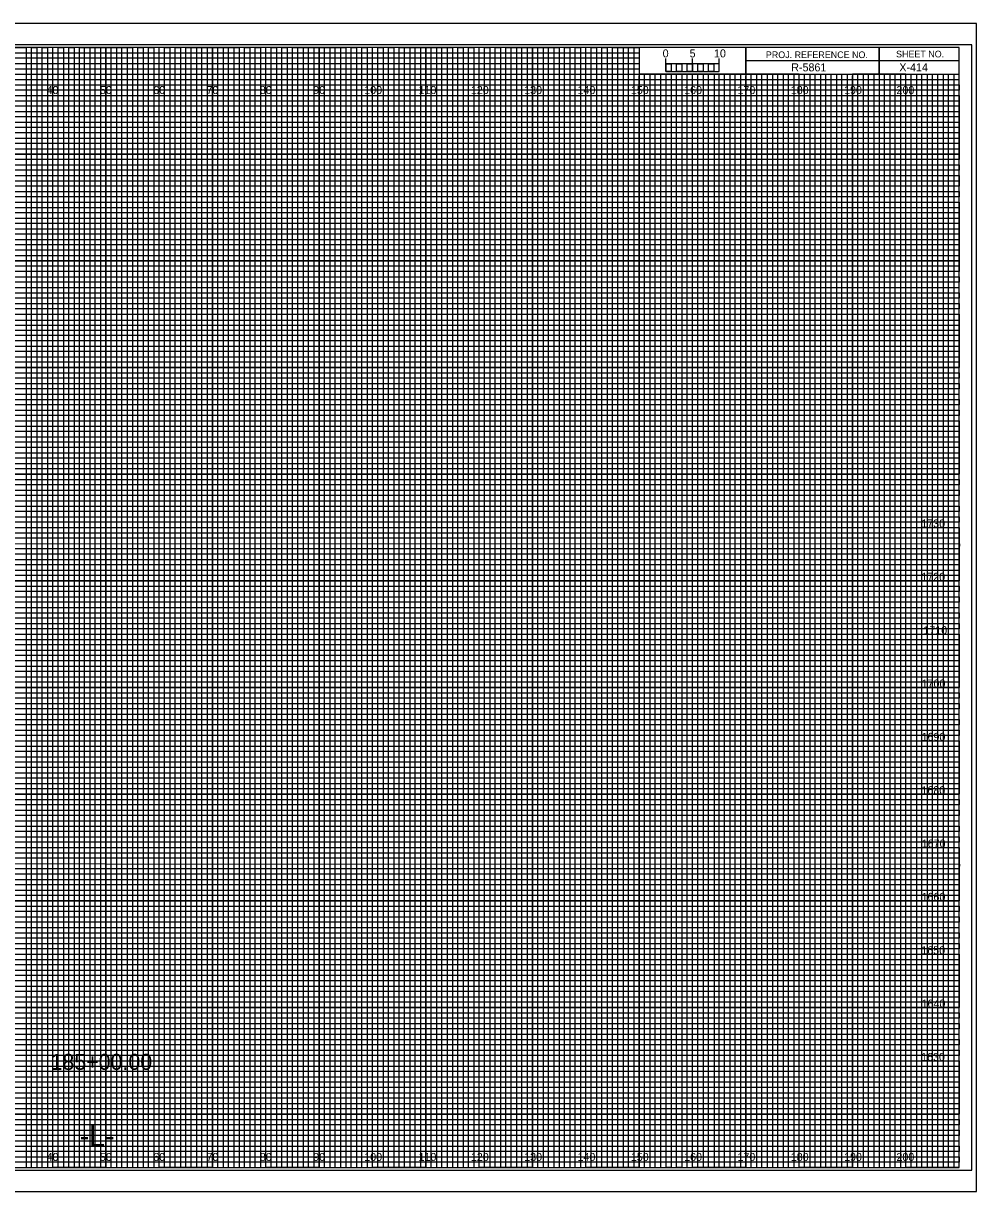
# Model space of a CAD drawing. Extents: x -13 to 323, y -5 to 6154.
# Drawn here: x 144.5 to 323.3, y 2195.5 to 2414.5 of the extents above; entities that cross this region are included whole.
import ezdxf

# ---------------------------------------------------------------- set-up
doc = ezdxf.new("R2010")
doc.units = 0
for name, color, linetype in [('Exist CMT Ground Line', 7, 'Continuous'), ('Prop Horizontal Alignment', 7, 'Continuous'), ('Prop Retaining Wall', 7, 'Continuous'), ('Prop XS Alignment Label', 7, 'Continuous'), ('Prop XS Bar Scale Labels', 7, 'Continuous'), ('Prop XS DDE', 7, 'Continuous'), ('Prop XS DDE Elevations', 7, 'Continuous'), ('Prop XS DDE Slope Text', 7, 'Continuous'), ('Prop XS Earthwork Shape', 7, 'Continuous'), ('Prop XS Elevation Labels', 7, 'Continuous'), ('Prop XS Project Number', 7, 'Continuous'), ('Prop XS Sheet Number', 7, 'Continuous'), ('Prop XS Station Labels', 7, 'Continuous'), ('Raster_Level_0', 7, 'Continuous'), ('Scratch_Level_3', 7, 'Continuous'), ('Sheet Cutting Line CELL', 7, 'Continuous')]:
    doc.layers.add(name, color=color, linetype=linetype)

msp = doc.modelspace()

# ---------------------------------------------------------------- linework, layer by layer
at = {"layer": 'Exist CMT Ground Line'}
for p, q in [((265, 2405.49), (265, 2407.9)), ((265, 2406.9), (265, 2407.9)), ((270, 2405.49), (270, 2407.9)), ((275, 2405.49), (275, 2407.9)), ((275, 2406.9), (275, 2407.9))]:
    msp.add_line(p, q, dxfattribs=at)
for points in [[(275, 2406.9), (265, 2406.9), (265, 2405.49), (275, 2405.49)], [(265, 2406.9), (266, 2406.9), (266, 2405.49), (265, 2405.49)], [(267, 2406.9), (268, 2406.9), (268, 2405.49), (267, 2405.49)], [(269, 2406.9), (270, 2406.9), (270, 2405.49), (269, 2405.49)], [(271, 2406.9), (272, 2406.9), (272, 2405.49), (271, 2405.49)], [(273, 2406.9), (274, 2406.9), (274, 2405.49), (273, 2405.49)]]:
    msp.add_lwpolyline(points, close=True, dxfattribs=at)
at = {"layer": 'Prop Retaining Wall'}
for p, q in [((0, 2409), (260, 2409)), ((260, 2409), (260, 2407.98)), ((260, 2407.98), (0, 2407.98)), ((0, 2407), (260, 2407)), ((260, 2407), (260, 2405.89)), ((260, 2405.89), (0, 2405.89)), ((0, 2404), (320, 2404))]:
    msp.add_line(p, q, dxfattribs=at)
for points in [[(0, 2403), (270, 2403), (320, 2403), (320, 2402), (0, 2402)], [(0, 2401), (320, 2401), (320, 2399), (0, 2399)], [(0, 2398), (320, 2398), (320, 2397), (0, 2396.98)], [(0, 2396), (320, 2396), (320, 2394), (0, 2394)], [(0, 2393), (320, 2393), (320, 2392), (0, 2392)], [(0, 2391), (320, 2391), (320, 2389), (0, 2389)], [(0, 2388), (320, 2388), (320, 2387), (0, 2387)], [(0, 2386), (320, 2386), (320, 2384), (0, 2384)], [(0, 2383), (320, 2383), (320, 2382), (0, 2382)], [(0, 2381), (320, 2381), (320, 2379), (0, 2379)], [(0, 2378), (320, 2378), (320, 2377), (0, 2377)], [(0, 2376), (320, 2376), (320, 2373.95), (320, 2373), (320, 2372), (0, 2372)], [(0, 2374), (320, 2374), (320, 2373), (0, 2373)], [(0, 2371), (320, 2371), (320, 2369), (0, 2369.03)], [(0, 2369.03), (320, 2369), (320, 2368), (0, 2368)], [(0, 2367), (320, 2367), (320, 2366), (0, 2366)], [(0, 2364), (320, 2364), (320, 2363), (0, 2363)], [(0, 2362), (320, 2362), (320, 2361), (0, 2361)], [(-0.07, 2358.89), (320, 2358.89), (320, 2357.88), (-0.07, 2357.88)], [(0, 2357), (320, 2357), (320, 2356), (0, 2356)], [(0, 2354), (320, 2354), (320, 2353), (0, 2353)], [(0, 2352), (320, 2352), (320, 2351), (0, 2351)], [(0, 2349), (320, 2349), (320, 2348), (0, 2348)], [(0, 2347), (320, 2347), (320, 2346), (0, 2346)], [(0, 2344), (320, 2344), (320, 2343), (0, 2343)], [(0, 2342), (320, 2342), (320, 2341), (0, 2341)], [(0, 2339), (320, 2339), (319.99, 2337.98), (0, 2338)], [(0, 2337), (320, 2337), (320, 2336), (0, 2336)], [(0, 2334), (320, 2334), (320, 2333), (0, 2333)], [(0, 2332), (320, 2332), (320, 2331), (0, 2331)], [(0, 2329), (320, 2329), (320, 2328), (0, 2328)], [(0, 2327), (320, 2327), (320, 2326), (0, 2326)], [(0, 2324), (320, 2324), (320, 2323), (0, 2323)], [(0, 2322), (320, 2322), (320, 2321), (0, 2321)], [(0, 2319), (320, 2319), (320, 2318), (0, 2318)], [(0, 2316.99), (320.07, 2316.91), (320, 2316), (0, 2316)], [(0, 2314), (320, 2314), (320, 2313), (0, 2313)], [(0, 2312), (320, 2312), (320, 2311), (0, 2311)], [(0, 2309), (320, 2309), (320, 2308), (0, 2308)], [(0, 2307), (320, 2307), (320, 2306), (0, 2306)], [(0, 2304), (320, 2304), (320, 2303), (0, 2303)], [(0, 2302), (320, 2302), (320, 2301), (0, 2301)], [(0, 2299), (320, 2299), (320, 2298), (0, 2298)], [(0, 2297), (320, 2297), (320, 2296), (0, 2296)], [(0, 2294), (320, 2294), (320, 2293), (0, 2293)], [(0, 2292), (320, 2292), (320, 2291), (0, 2291)], [(0, 2289), (320, 2289), (320, 2288), (0, 2288)], [(0, 2287), (320, 2287), (320, 2286), (0, 2286)], [(0, 2284), (320, 2284), (320, 2283), (0, 2283)], [(0, 2282), (320, 2282), (320, 2281), (0, 2281)], [(0, 2279), (320, 2279), (319.99, 2277.98), (0, 2278)], [(0, 2277), (320, 2277), (320, 2276), (0, 2276)], [(0, 2274), (320, 2274), (320, 2273), (0, 2273)], [(0, 2272), (320, 2272), (320, 2271), (0, 2271)], [(0, 2269), (320, 2269), (320, 2268), (0, 2268)], [(0, 2267), (320, 2267), (320, 2266), (0, 2266)], [(0, 2264), (320, 2264), (320, 2263), (0, 2263)], [(0, 2262), (320, 2262), (320, 2261), (0, 2261)], [(0, 2259), (320, 2259), (320, 2258), (0, 2258)], [(0, 2256.99), (320.07, 2256.91), (320, 2256), (0, 2256)], [(0, 2254), (320, 2254), (320, 2253), (0, 2253)], [(0, 2252), (320, 2252), (320, 2251), (0, 2251)], [(0, 2249), (320, 2249), (320, 2248), (0, 2248)], [(0, 2247), (320, 2247), (320, 2246), (0, 2246)], [(0, 2244), (320, 2244), (320, 2243), (0, 2243)], [(0, 2242), (320, 2242), (320, 2241), (0, 2241)], [(0, 2239), (320, 2239), (320, 2238), (0, 2238)], [(0, 2237), (320, 2237), (320, 2236), (0, 2236)], [(0, 2234), (320, 2234), (320, 2233), (0, 2233)], [(0, 2232), (320, 2232), (320, 2231), (0, 2231)], [(0, 2229), (320, 2229), (320, 2228), (0, 2228)], [(0, 2227), (320, 2227), (320, 2226), (0, 2226)], [(0, 2224), (320, 2224), (320, 2223), (0, 2223)], [(0, 2222), (320, 2222), (320, 2221), (0, 2221)], [(0, 2219), (320, 2219), (320, 2218), (0, 2218)], [(0, 2217), (320, 2217), (320, 2216), (0, 2216)], [(0, 2214), (320, 2214), (320, 2213), (0, 2213)], [(0, 2212), (320, 2212), (320, 2211), (0, 2211)], [(0, 2209), (320, 2209), (320, 2208), (0, 2208)], [(0, 2207), (320, 2207), (320, 2206), (0, 2206)], [(0, 2204), (320, 2204), (320, 2203), (0, 2203)], [(0, 2202), (320, 2202), (320, 2201), (0, 2201)]]:
    msp.add_lwpolyline(points, dxfattribs=at)
at = {"layer": 'Prop XS Alignment Label'}
for p, q in [((305, 2410), (305, 2405)), ((305, 2405), (305, 2410)), ((280, 2407.5), (280, 2405)), ((320, 2407.49), (280, 2407.49)), ((280, 2405), (320, 2405))]:
    msp.add_line(p, q, dxfattribs=at)
for points in [[(320, 2410), (0, 2410), (0, 2200), (320, 2200)], [(280, 2410), (260, 2410), (260, 2405.03), (280, 2405.03)], [(320, 2410), (280, 2410), (280, 2405), (320, 2405)]]:
    msp.add_lwpolyline(points, close=True, dxfattribs=at)
at = {"layer": 'Prop XS DDE'}
msp.add_lwpolyline([(-13.4, 2195.5), (323.3, 2195.5), (323.3, 2414.5), (-13.4, 2414.5)], close=True, dxfattribs=at)
at = {"layer": 'Prop XS DDE Elevations'}
for p, q in [((150, 2200), (150, 2410)), ((160, 2200), (160, 2410)), ((170, 2200), (170, 2410)), ((180, 2200), (180, 2410)), ((190, 2200), (190, 2410)), ((200, 2200), (200, 2410)), ((210, 2200), (210, 2410)), ((220, 2200), (220, 2410)), ((230, 2200), (230, 2410)), ((240, 2200), (240, 2410)), ((250, 2200), (250, 2410)), ((260, 2200), (260, 2404.69)), ((270, 2200), (270, 2404.69)), ((280, 2200), (280, 2404.69)), ((290, 2200), (290, 2404.69)), ((300, 2200), (300, 2404.69)), ((310, 2200), (310, 2404.69)), ((0, 2400), (320, 2400)), ((0, 2390), (320, 2390)), ((0, 2380), (320, 2380)), ((0, 2370), (320, 2370)), ((0, 2360), (320, 2360)), ((0, 2350), (320, 2350)), ((0, 2340), (320, 2340)), ((0, 2330), (320, 2330)), ((0, 2320), (320, 2320)), ((0, 2310), (320, 2310)), ((0, 2300), (320, 2300)), ((0, 2290), (320, 2290)), ((0, 2280), (320, 2280)), ((0, 2270), (320, 2270)), ((0, 2260), (320, 2260)), ((0, 2250), (320, 2250)), ((0, 2240), (320, 2240)), ((0, 2230), (320, 2230)), ((0, 2220), (320, 2220)), ((0, 2210), (320, 2210))]:
    msp.add_line(p, q, dxfattribs=at)
at = {"layer": 'Prop XS DDE Slope Text'}
msp.add_lwpolyline([(-10.8, 2199.5), (322.4, 2199.5), (322.4, 2410.5), (-10.8, 2410.5)], close=True, dxfattribs=at)
at = {"layer": 'Prop XS Earthwork Shape'}
for p, q in [((150, 2410), (140, 2410)), ((150, 2200), (150, 2410)), ((170, 2410), (160, 2410)), ((160, 2410), (160, 2200)), ((170, 2200), (170, 2410)), ((190, 2410), (180, 2410)), ((180, 2410), (180, 2200)), ((190, 2200), (190, 2410)), ((210, 2410), (200, 2410)), ((200, 2410), (200, 2200)), ((210, 2200), (210, 2410)), ((230, 2410), (220, 2410)), ((220, 2410), (220, 2200)), ((230, 2200), (230, 2410)), ((250, 2410), (240, 2410)), ((240, 2410), (240, 2200)), ((250, 2200), (250, 2410)), ((260, 2410), (260, 2200)), ((270, 2200), (270, 2405)), ((290, 2405), (280, 2405)), ((280, 2405), (280, 2200)), ((290, 2200), (290, 2405)), ((310, 2405), (300, 2405)), ((300, 2405), (300, 2200)), ((310, 2200), (310, 2405)), ((160, 2200), (150, 2200)), ((180, 2200), (170, 2200)), ((200, 2200), (190, 2200)), ((220, 2200), (210, 2200)), ((240, 2200), (230, 2200)), ((260, 2200), (250, 2200)), ((280, 2200), (270, 2200)), ((300, 2200), (290, 2200)), ((320, 2200), (310, 2200)), ((320, 2200), (320, 2200))]:
    msp.add_line(p, q, dxfattribs=at)
for points in [[(0, 2400), (320, 2400), (320, 2390), (0, 2390)], [(0, 2380), (320, 2380), (320, 2370), (0, 2370)], [(0, 2360), (320, 2360), (320, 2350), (0, 2350)], [(0, 2340), (320, 2340), (320, 2330), (0, 2330)], [(0, 2320), (320, 2320), (320, 2310), (0, 2310)], [(0, 2300), (320, 2300), (320, 2290), (0, 2290)], [(0, 2280), (320, 2280), (320, 2270), (0, 2270)], [(0, 2260), (320, 2260), (320, 2250), (0, 2250)], [(0, 2240), (320, 2240), (320, 2230), (0, 2230)], [(0, 2220), (320, 2220), (320, 2210), (0, 2210)]]:
    msp.add_lwpolyline(points, dxfattribs=at)
at = {"layer": 'Prop XS Elevation Labels'}
for p, q in [((267, 2405), (266.01, 2405)), ((266.01, 2405), (266.01, 2200)), ((267, 2200), (267, 2405)), ((269, 2405), (268, 2405)), ((268, 2405), (268, 2200)), ((269, 2200), (269, 2405)), ((266.01, 2200), (265, 2200)), ((268, 2200), (267, 2200))]:
    msp.add_line(p, q, dxfattribs=at)
for points in [[(145, 2200), (146, 2200), (146, 2410), (147, 2410), (147, 2200)], [(147, 2200), (148, 2200), (148, 2410), (149, 2410), (149, 2200)], [(150, 2200), (151, 2200), (151, 2410), (152, 2410), (152, 2200)], [(152, 2200), (153, 2200), (153, 2410), (154, 2410), (154, 2200)], [(155, 2200), (156, 2200), (156, 2410), (157, 2410), (157, 2200)], [(157, 2200), (158, 2200), (158, 2410), (159, 2410), (159, 2200)], [(160, 2200), (161, 2200), (161, 2410), (162, 2410), (162, 2200)], [(162, 2200), (163, 2200), (163, 2410), (164, 2410), (164, 2200)], [(165, 2200), (166, 2200), (166, 2410), (167, 2410), (167, 2200)], [(167, 2200), (168, 2200), (168, 2410), (169, 2410), (169, 2200)], [(170, 2200), (171, 2200), (171, 2410), (172, 2410), (172, 2200)], [(172, 2200), (173, 2200), (173, 2410), (174, 2410), (174, 2200)], [(175, 2200), (176, 2200), (176, 2410), (177, 2410), (177, 2200)], [(177, 2200), (178, 2200), (178, 2410), (179, 2410), (179, 2200)], [(180, 2200), (181, 2200), (181, 2410), (182, 2410), (182, 2200)], [(182, 2200), (183, 2200), (183, 2410), (184, 2410), (184, 2200)], [(185, 2200), (186, 2200), (186, 2410), (187, 2410), (187, 2200)], [(187, 2200), (188, 2200), (188, 2410), (189, 2410), (189, 2200)], [(190, 2200), (191, 2200), (191, 2410), (192, 2410), (192, 2200)], [(192, 2200), (193, 2200), (193, 2410), (194, 2410), (194, 2200)], [(195, 2200), (196, 2200), (196, 2410), (197, 2410), (197, 2200)], [(197, 2200), (198, 2200), (198, 2410), (199, 2410), (199, 2200)], [(200, 2200), (201, 2200), (201, 2410), (202, 2410), (202, 2200)], [(202, 2200), (203, 2200), (203, 2410), (204, 2410), (204, 2200)], [(205, 2200), (206, 2200), (206, 2410), (207, 2410), (207, 2200)], [(207, 2200), (208, 2200), (208, 2410), (209, 2410), (209, 2200)], [(210, 2200), (211, 2200), (211, 2410), (212, 2410), (212, 2200)], [(212, 2200), (213, 2200), (213, 2410), (214, 2410), (214, 2200)], [(215, 2200), (216, 2200), (216, 2410), (217, 2410), (217, 2200)], [(217, 2200), (218, 2200), (218, 2410), (219, 2410), (219, 2200)], [(220, 2200), (221, 2200), (221, 2410), (222, 2410), (222, 2200)], [(222, 2200), (223, 2200), (223, 2410), (224, 2410), (224, 2200)], [(225, 2200), (226, 2200), (226, 2410), (227, 2410), (227, 2200)], [(227, 2200), (228, 2200), (228, 2410), (229, 2410), (229, 2200)], [(230, 2200), (231, 2200), (231, 2410), (232, 2410), (232, 2200)], [(232, 2200), (233, 2200), (233, 2410), (234, 2410), (234, 2200)], [(235, 2200), (236, 2200), (236, 2410), (237, 2410), (237, 2200)], [(237, 2200), (238, 2200), (238, 2410), (239, 2410), (239, 2200)], [(240, 2200), (241, 2200), (241, 2410), (242, 2410), (242, 2200)], [(242, 2200), (243, 2200), (243, 2410), (244, 2410), (244, 2200)], [(245, 2200), (246, 2200), (246, 2410), (247, 2410), (247, 2200)], [(247, 2200), (248, 2200), (248, 2410), (249, 2410), (249, 2200)], [(250, 2200), (251, 2200), (251, 2410), (252, 2410), (252, 2200)], [(252, 2200), (253, 2200), (253, 2410), (254, 2410), (254, 2200)], [(255, 2200), (256, 2200), (256, 2410), (257, 2410), (257, 2200)], [(257, 2200), (258, 2200), (258, 2410), (259, 2410), (259, 2200)], [(260, 2200), (261, 2200), (261, 2405), (262.02, 2405), (262.02, 2200)], [(262, 2200), (263, 2200), (263, 2405), (263.99, 2405), (263.99, 2200)], [(270, 2200), (270.98, 2200), (270.98, 2405), (272, 2405), (272, 2200)], [(272, 2200), (273, 2200), (273, 2405), (274.05, 2405), (274.05, 2200)], [(275, 2200), (276, 2200), (276, 2405), (277, 2405), (277, 2200)], [(277, 2200), (278, 2200), (278, 2405), (279, 2405), (279, 2200)], [(280, 2200), (281, 2200), (281, 2405), (282, 2405), (282, 2200)], [(282, 2200), (283, 2200), (283, 2405), (284, 2405), (284, 2200)], [(285, 2200), (286, 2200), (286, 2405), (287, 2405), (287, 2200)], [(287, 2200), (288, 2200), (288, 2405), (289, 2405), (289, 2200)], [(290, 2200), (291, 2200), (291, 2405), (292, 2405), (292, 2200)], [(292, 2200), (293, 2200), (293, 2405), (294, 2405), (294, 2200)], [(295, 2200), (296, 2200), (296, 2405), (297, 2405), (297, 2200)], [(297, 2200), (298, 2200), (298, 2405), (299, 2405), (299, 2200)], [(300, 2200), (301, 2200), (301, 2405), (302, 2405), (302, 2200)], [(302, 2200), (303, 2200), (303, 2405), (304, 2405), (304, 2200)], [(305, 2200), (306, 2200), (306, 2405), (307, 2405), (307, 2200)], [(307, 2200), (308, 2200), (308, 2405), (309, 2405), (309, 2200)], [(310, 2200), (311, 2200), (311, 2405), (312, 2405), (312, 2200)], [(312, 2200), (313, 2200), (313, 2405), (314, 2405), (314, 2200)], [(315, 2200), (316, 2200), (316, 2405), (317, 2405), (317, 2200)], [(317, 2200), (318, 2200), (318, 2405), (319, 2405), (319, 2200)]]:
    msp.add_lwpolyline(points, dxfattribs=at)
at = {"layer": 'Prop XS Station Labels'}
for points in [[(135, 2410), (145, 2410), (145, 2200), (155, 2200), (155, 2410), (165, 2410), (165, 2200), (175, 2200), (175, 2410), (185, 2410), (185, 2200), (195, 2200), (195, 2410), (205, 2410), (205, 2200), (215, 2200), (215, 2410), (225, 2410), (225, 2200), (235, 2200), (235, 2410), (245, 2410), (245, 2200), (255, 2200), (255, 2410), (259.93, 2410), (260, 2410), (260, 2405), (264.99, 2405), (264.99, 2200), (275, 2200), (275, 2405), (285, 2405), (285, 2200), (295, 2200), (295, 2405), (305, 2405), (305, 2200), (315, 2200), (315, 2405)], [(0, 2405), (275, 2405)], [(0, 2385), (320, 2385), (320, 2395), (0, 2395)], [(0, 2365), (320, 2365), (320, 2375), (0, 2375)], [(0, 2345), (320, 2345), (320, 2355), (0, 2355)], [(0, 2325), (320, 2325), (320, 2335), (0, 2335)], [(0, 2305), (320, 2305), (320, 2315), (0, 2315)], [(0, 2285), (320, 2285), (320, 2295), (0, 2295)], [(0, 2265), (320, 2265), (320, 2275), (0, 2275)], [(0, 2245), (320, 2245), (320, 2255), (0, 2255)], [(0, 2225), (320, 2225), (320, 2235), (0, 2235)], [(0, 2205), (320, 2205), (320, 2215), (0, 2215)]]:
    msp.add_lwpolyline(points, dxfattribs=at)
at = {"layer": 'Sheet Cutting Line CELL'}
for p, q in [((323.3, 2414.5), (-13.4, 2414.5)), ((-13.4, 2195.5), (323.3, 2195.5))]:
    msp.add_line(p, q, dxfattribs=at)

# ---------------------------------------------------------------- texts
at = {"layer": 'Exist CMT Ground Line'}
msp.add_text('0', height=1.5, dxfattribs=at).set_placement((264.41, 2408.12))
at = {"layer": 'Prop Horizontal Alignment'}
msp.add_text('185+00.00', height=3, dxfattribs=at).set_placement((149.59, 2218.33))
at = {"layer": 'Prop XS Alignment Label'}
for s, height, p in [('PROJ. REFERENCE NO.', 1.25, (283.77, 2407.99)), ('SHEET NO.', 1.25, (308.19, 2408.12)), ('-L-', 4, (155.06, 2204))]:
    msp.add_text(s, height=height, dxfattribs=at).set_placement(p)
at = {"layer": 'Prop XS Bar Scale Labels'}
for s, p in [('5', (269.47, 2408.12)), ('10', (274.04, 2408.12))]:
    msp.add_text(s, height=1.5, dxfattribs=at).set_placement(p)
at = {"layer": 'Prop XS Project Number'}
msp.add_text('R-5861', height=1.5, dxfattribs=at).set_placement((288.53, 2405.5))
at = {"layer": 'Prop XS Sheet Number'}
msp.add_text('X-414', height=1.5, dxfattribs=at).set_placement((308.8, 2405.51))
at = {"layer": 'Raster_Level_0'}
for s, p in [('40', (148.86, 2401.25)), ('50', (158.86, 2401.25)), ('60', (168.86, 2401.25)), ('70', (178.86, 2401.25)), ('80', (188.86, 2401.25)), ('90', (198.86, 2401.25)), ('100', (208.44, 2401.25)), ('110', (218.62, 2401.25)), ('120', (228.44, 2401.25)), ('130', (238.44, 2401.25)), ('140', (248.44, 2401.25)), ('150', (258.44, 2401.25)), ('160', (268.44, 2401.25)), ('170', (278.44, 2401.25)), ('180', (288.44, 2401.25)), ('190', (298.44, 2401.25)), ('200', (308.26, 2401.25)), ('40', (148.86, 2201.25)), ('50', (158.86, 2201.25)), ('60', (168.86, 2201.25)), ('70', (178.86, 2201.25)), ('80', (188.86, 2201.25)), ('90', (198.86, 2201.25)), ('100', (208.44, 2201.25)), ('110', (218.62, 2201.25)), ('120', (228.44, 2201.25)), ('130', (238.44, 2201.25)), ('140', (248.44, 2201.25)), ('150', (258.44, 2201.25)), ('160', (268.44, 2201.25)), ('170', (278.44, 2201.25)), ('180', (288.44, 2201.25)), ('190', (298.44, 2201.25)), ('200', (308.26, 2201.25))]:
    msp.add_text(s, height=1.5, dxfattribs=at).set_placement(p)
at = {"layer": 'Scratch_Level_3'}
for s, p in [('1730', (312.92, 2320)), ('1720', (312.93, 2310)), ('1710', (313.31, 2300)), ('1700', (312.98, 2290)), ('1690', (312.97, 2280)), ('1680', (312.95, 2270)), ('1670', (313, 2260)), ('1660', (312.97, 2250)), ('1650', (312.92, 2240)), ('1640', (312.97, 2230)), ('1630', (312.89, 2220))]:
    msp.add_text(s, height=1.5, dxfattribs=at).set_placement(p)

doc.saveas('drawing.dxf')
